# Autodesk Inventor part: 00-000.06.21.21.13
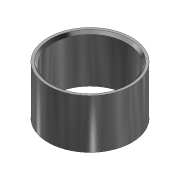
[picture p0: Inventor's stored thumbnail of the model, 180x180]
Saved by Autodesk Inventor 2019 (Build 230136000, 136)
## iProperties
Created: 2019-01
Part Number: 00-000.06.21.21.13
Material: Steel, Mild
Document SubType Name: Modeling
Designer: m.vorobev
Density: 7.85 g/cm^3
Appearance: Semi-Polished
Author: m.vorobev
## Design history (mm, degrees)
derived "00-000.06.21.21.11,12,13.ipt"
feature "Solid1::00-000.06.21.21.11,12,13.ipt"
tag "TaggingFeature1"
body "Solid1"
other parameters: "D1" = 51, "D" = 45, "d4" = 1.5
